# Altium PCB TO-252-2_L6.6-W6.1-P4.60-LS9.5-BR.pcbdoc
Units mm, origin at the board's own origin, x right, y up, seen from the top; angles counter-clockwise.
Board outline 24.22 x 19.83 mm, 2 copper layers (Top Layer, Bottom Layer), stack 0 mm thick; 1 components, 0 nets, 3 pads, 0 vias.
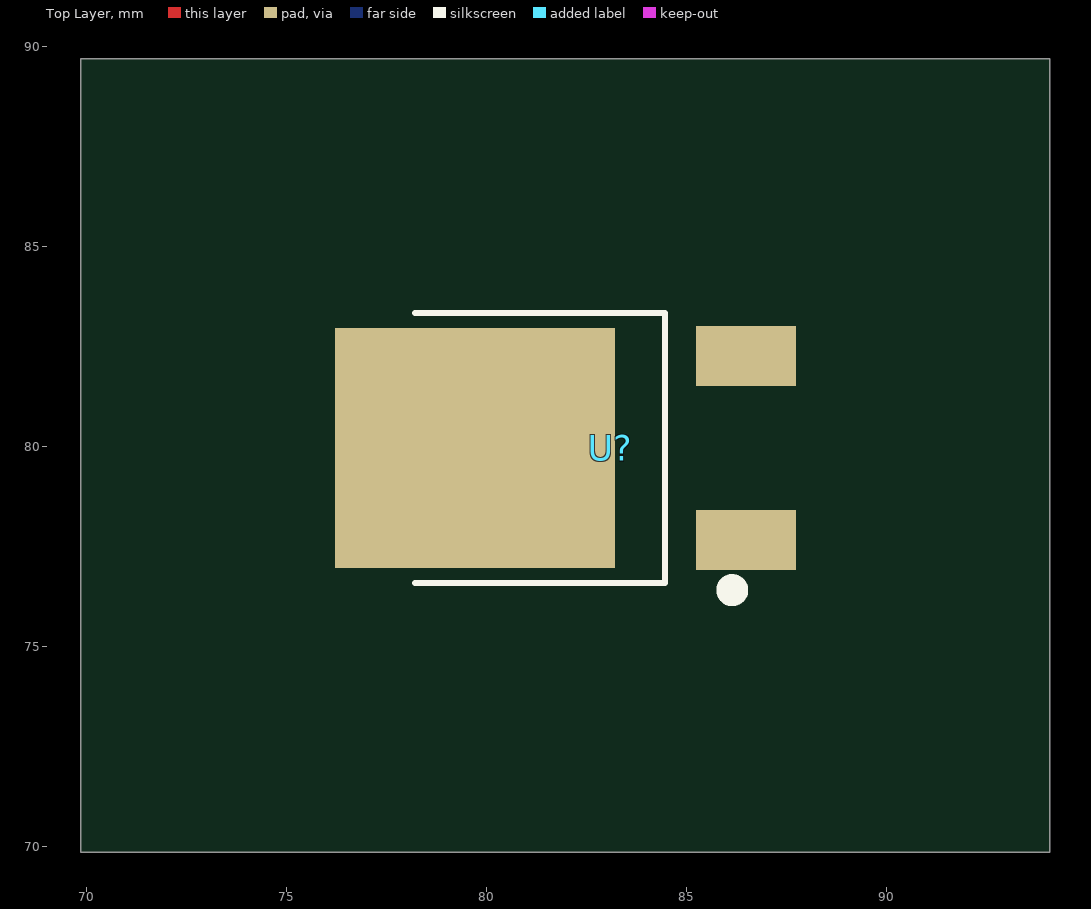
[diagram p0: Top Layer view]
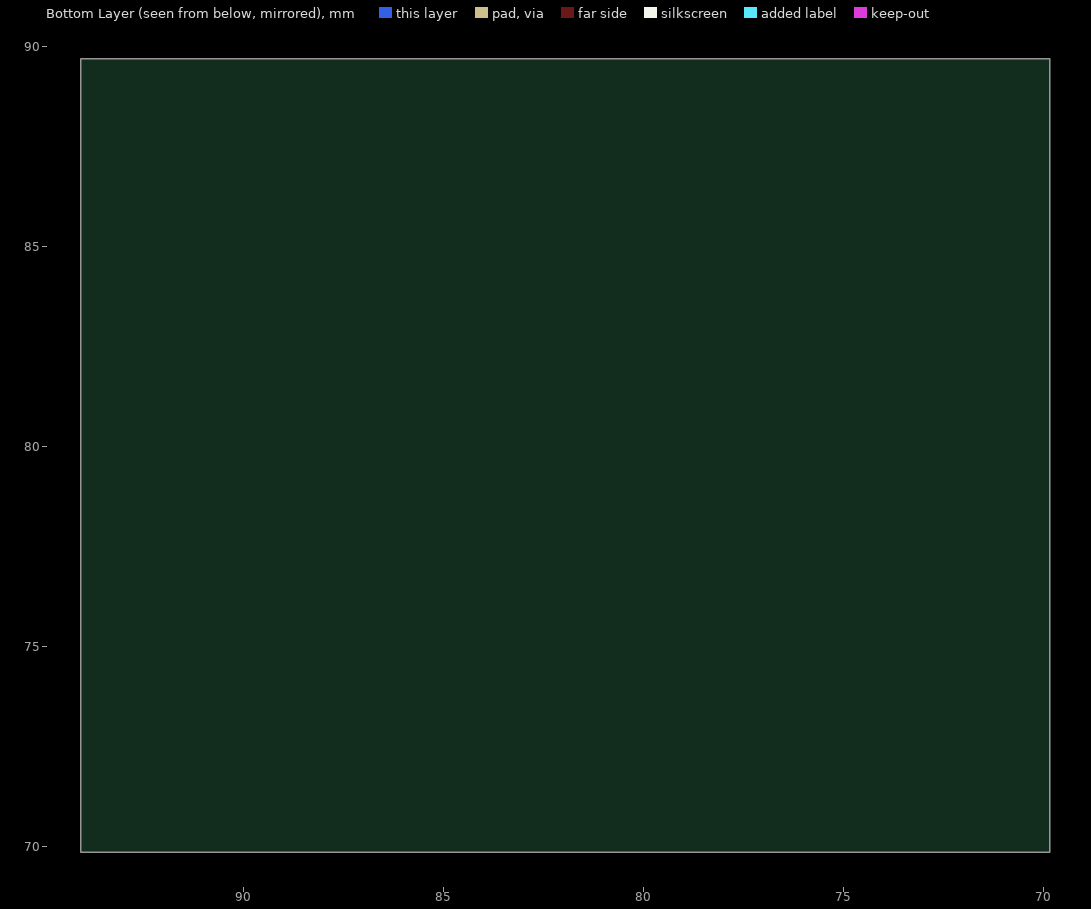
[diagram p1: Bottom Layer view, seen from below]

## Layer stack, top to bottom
Top Layer: signal copper (thickness not stored)
Bottom Layer: signal copper (thickness not stored)

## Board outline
94.074,69.85 69.85,69.85 69.85,89.682 94.074,89.682

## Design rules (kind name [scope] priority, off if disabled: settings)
PasteMaskExpansion "Paste Mask Expansion" [All] p1: expansion=0
SolderMaskExpansion "Solder Mask Expansion" [IsVia] p1: expansion=-25.4 istentingtop=TRUE
SolderMaskExpansion "Solder Mask Expansion" [All] p2: expansion=0.051 istentingtop=FALSE

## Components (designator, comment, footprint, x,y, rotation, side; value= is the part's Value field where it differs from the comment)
U? "" TO-252-2_L6.6-W6.1-P4.60-LS9.5-BR 83.087,79.956 r0 top

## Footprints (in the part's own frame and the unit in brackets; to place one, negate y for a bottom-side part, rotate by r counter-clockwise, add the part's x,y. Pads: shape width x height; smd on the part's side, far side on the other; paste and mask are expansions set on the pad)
TO-252-2_L6.6-W6.1-P4.60-LS9.5-BR [mm]
  rect 2.5x1.5 smd: 1(3.387,-2.3) 3(3.387,2.3)
  rect 7x6 smd: 2(-3.387,0)
  silkscreen extent -4.89,-3.76 3.25,3.38

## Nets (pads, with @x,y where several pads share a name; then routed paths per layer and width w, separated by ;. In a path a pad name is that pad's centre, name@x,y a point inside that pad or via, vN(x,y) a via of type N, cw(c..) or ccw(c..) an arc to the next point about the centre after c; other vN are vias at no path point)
pads on no net: U?.1 U?.2 U?.3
